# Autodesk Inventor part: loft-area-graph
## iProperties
Created: 2007-05
Part Number: loft-area-graph
Document SubType Name: Modeling
Designer: Administrator
Density: 1 g/cm^3
Author: Administrator
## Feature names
1. Loft1
